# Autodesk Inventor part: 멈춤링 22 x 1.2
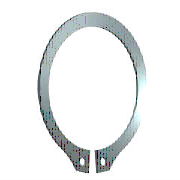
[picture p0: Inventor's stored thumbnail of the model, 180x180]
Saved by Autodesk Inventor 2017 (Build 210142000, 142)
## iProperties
IsCustomPart: 0
Created: 2021-07
Part Number: 멈춤링 22 x 1.2
Material: 강철, 연강
Description: 리테이닝 링(C형)
Document SubType Name: Modeling
Standard: KS B 1336
Designer: mdu
Standards Organization: KS
Language: ko-KR
Size Designation: 22 x 1.2
Categories: <MemberInstance><Categories><Category DisplayName="샤프트 부품" InternalName="7f7aeb1f-a693-4053-b835-cee3144e0d98" Mnemonic="SHFT"><Category DisplayName="써클립" Inter
Density: 7.86 g/cm^3
Mass: 1.82859 g
Surface Area: 5.91219 cm^2
Volume: 0.232645 cm^3
Appearance: 파란색 - 벽 페인트 - 광택
Author: mdu
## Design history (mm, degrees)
sketch "스케치1"
  geometry: L1 (-6, 0)-(6, 0) reference; L2 (0, 20.189)-(0, -80.536) reference; L3 (-48.09, 0)-(48.09, 0) reference; L4 (-0.5, -21.488)-(-0.5, -25.588); L5 (-0.5, -6.54)-(-0.5, -13.29); L6 (-2.795, 2.7)-(3.672, 2.7); L7 (0.5, -6.54)-(0.5, -13.29); L8 (0.5, -21.488)-(0.5, -25.588); C1 r 1 at (-2, -23.437); C2 r 1 at (2, -23.437); A1 r 10.5 centre (0, -11) between (0.5, -21.488) and (-0.5, -21.488); A2 r 13.025 centre (0, -10.325) between (5.149, -22.289) and (-5.149, -22.289); A3 r 14.597 centre (0, -11) between (-2.318, -25.411) and (-0.5, -25.588); A4 r 2 centre (-2, -23.437) between (-3.97, -23.781) and (-2.318, -25.411); A5 r 2 centre (-5.94, -24.126) between (-3.97, -23.781) and (-5.149, -22.289); A6 r 2 centre (5.94, -24.126) between (5.149, -22.289) and (3.97, -23.781); A7 r 2 centre (2, -23.437) between (2.318, -25.411) and (3.97, -23.781); A8 r 14.597 centre (0, -11) between (0.5, -25.588) and (2.318, -25.411)
  constraints: 16 point on circle, 12 end point, 10 centre point, 9 symmetric about line, 5 point on line, 4 tangent, 3 coincident, 2 horizontal, 1 perpendicular, 1 vertical, 5 other
  dimensions: "d0" = 21 diameter of A1 (= ND); "d1" = 4.1 distance of L4.end L4.start (= SRB2); "d6" = 0.5 distance between parallel lines of L2 L5 (= 0.25 x SD5); "d7" = 2.7 distance between parallel lines of L6 L3 (= SRB1); "d8" = 0.675 distance of A1.centre A2.centre (= 0.25 x SRB1); "d9" = 2 radius of A4 (= SD5); "d10" = 2 radius of A5 (= SD5); "d11" = 1.5 distance from line of L4 A4.centre (= 0.75 x SD5); "d12" = 2 diameter of C1 (= SD5); "d13" = 2 diameter of C2 (= SD5); "d14" = 11 distance from line of A1.centre L1 (= 0.5 x WD)
extrude "본체" new body sketch "스케치1" distance "d2" = 1.2 (= SD); taper "d3" = 0 deg
workaxis "Work Axis1"
workplane "Work Plane1"
body "Solid1"
other parameters: "WD" = 22 (= WDMIN) [user parameter; used in 1 equation term], "SD" = 1.2 [user parameter; used in 1 equation term], "SRB1" = 2.7 [user parameter; used in 2 equation terms], "ND" = 21 [user parameter; used in 1 equation term], "SRB2" = 4.1 [user parameter; used in 1 equation term], "SD5" = 2 [user parameter; used in 6 equation terms], "d15" = 0, "d16" = 0, "d17" = 0, "d41" = 0, "d42" = 0, "WDMIN" = 22 [user parameter; used in 1 equation term], "SD3" = 20.5 [user parameter], "WDMAX" = 24 [user parameter]
